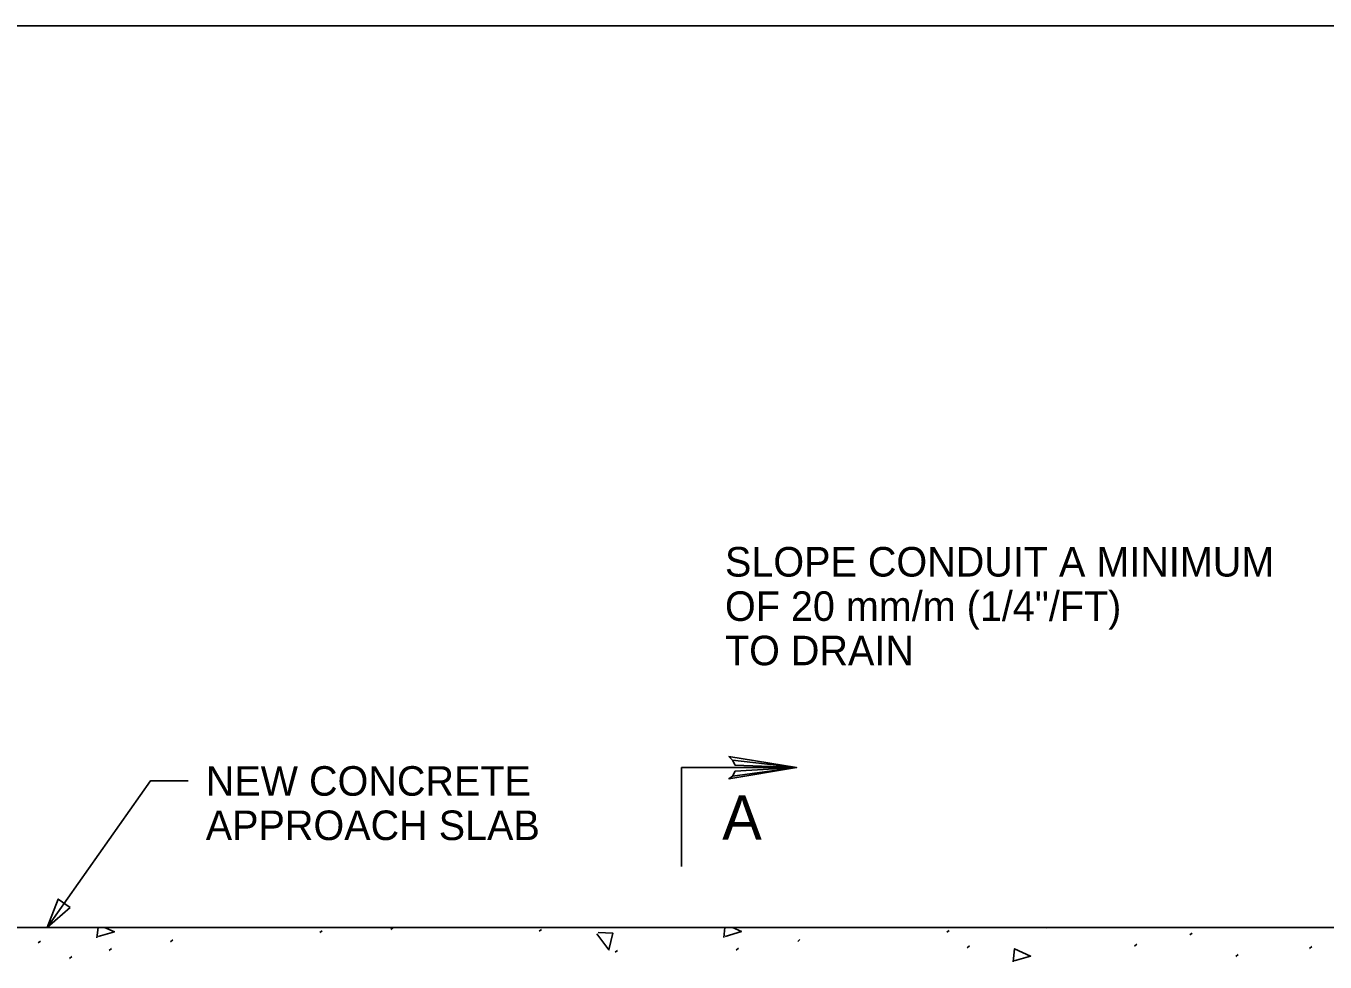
# Model space of a CAD drawing. Extents: x 3239 to 4230, y -4276 to -2494.
# Drawn here: x 3469.7 to 3601.5, y -3198.3 to -3103.3 of the extents above; entities that cross this region are included whole.
import ezdxf

# ---------------------------------------------------------------- set-up
doc = ezdxf.new("R2010")
doc.units = 0
doc.layers.add('2', color=7, linetype='Continuous')

msp = doc.modelspace()

# ---------------------------------------------------------------- linework, layer by layer
at = {"layer": '2'}
for p, q in [((4065.03, -3103.29), (3279.03, -3103.29)), ((3536.22, -3178.54), (3547.9, -3178.54)), ((3536.22, -3188.59), (3536.22, -3178.54)), ((3407.28, -3194.76), (3615.58, -3194.76)), ((3499.54, -3195.28), (3499.78, -3195.1)), ((3506.72, -3194.98), (3506.95, -3194.79)), ((3521.79, -3195.15), (3522.02, -3194.96)), ((3563.15, -3195.25), (3563.38, -3195.06)), ((3573.21, -3194.83), (3573.29, -3194.76)), ((3587.79, -3195.51), (3588.02, -3195.33)), ((3470.96, -3196.33), (3471.19, -3196.15)), ((3484.4, -3196.21), (3484.63, -3196.03)), ((3548.01, -3196.18), (3548.24, -3195.99)), ((3565.2, -3196.83), (3565.43, -3196.64)), ((3582.17, -3196.66), (3582.4, -3196.47)), ((3599.93, -3196.9), (3600.17, -3196.71)), ((3474.13, -3197.92), (3474.36, -3197.73)), ((3478.16, -3197.1), (3478.39, -3196.91)), ((3529.5, -3197.29), (3529.74, -3197.1)), ((3541.76, -3197.07), (3542, -3196.88)), ((3592.44, -3197.7), (3592.68, -3197.52))]:
    msp.add_line(p, q, dxfattribs=at)
for points in [[(3541.4, -3179.42), (3541.65, -3178.92), (3547.9, -3178.54), (3541.4, -3179.42), (3541.03, -3179.67), (3547.9, -3178.54), (3541.65, -3178.29), (3541.4, -3177.79), (3547.9, -3178.54), (3541.03, -3177.42), (3541.4, -3177.79)], [(3471.88, -3194.76), (3482.35, -3179.9), (3486.18, -3179.9)], [(3476.92, -3195.82), (3477.03, -3194.76)], [(3477.7, -3194.76), (3478.69, -3195.21), (3477.04, -3195.7)], [(3527.77, -3195.27), (3529.24, -3195.34), (3528.85, -3197.04), (3527.64, -3195.41)], [(3540.53, -3195.78), (3540.63, -3194.76)], [(3541.38, -3194.76), (3542.3, -3195.18), (3540.64, -3195.67)], [(3569.86, -3198.27), (3570, -3196.92), (3571.63, -3197.67), (3569.97, -3198.16)]]:
    msp.add_lwpolyline(points, dxfattribs=at)
msp.add_lwpolyline([(3474.22, -3192.74), (3471.88, -3194.76), (3473, -3191.88)], close=True, dxfattribs=at)

# ---------------------------------------------------------------- texts
for s, height, p in [('SLOPE CONDUIT A MINIMUM', 3, (3540.63, -3159.16)), ('OF 20 mm/m (1/4"/FT)', 3, (3540.63, -3163.66)), ('TO DRAIN', 3, (3540.63, -3168.16)), ('NEW CONCRETE', 3, (3487.96, -3181.4)), ('A', 4.5, (3540.35, -3185.86)), ('APPROACH SLAB', 3, (3487.96, -3185.9))]:
    msp.add_text(s, height=height, dxfattribs=at).set_placement(p)

doc.saveas('drawing.dxf')
